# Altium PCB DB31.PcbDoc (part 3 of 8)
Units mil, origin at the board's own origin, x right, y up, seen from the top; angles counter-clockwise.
Board outline 3236.22 x 4456.69 mil, 8 copper layers (Top Layer, MidLayer1, MidLayer2, GND-Layer5, MidLayer3, VCC, MidLayer4, Bottom Layer), stack 61.8 mil thick; 226 components, 469 nets, 1815 pads, 1562 vias.
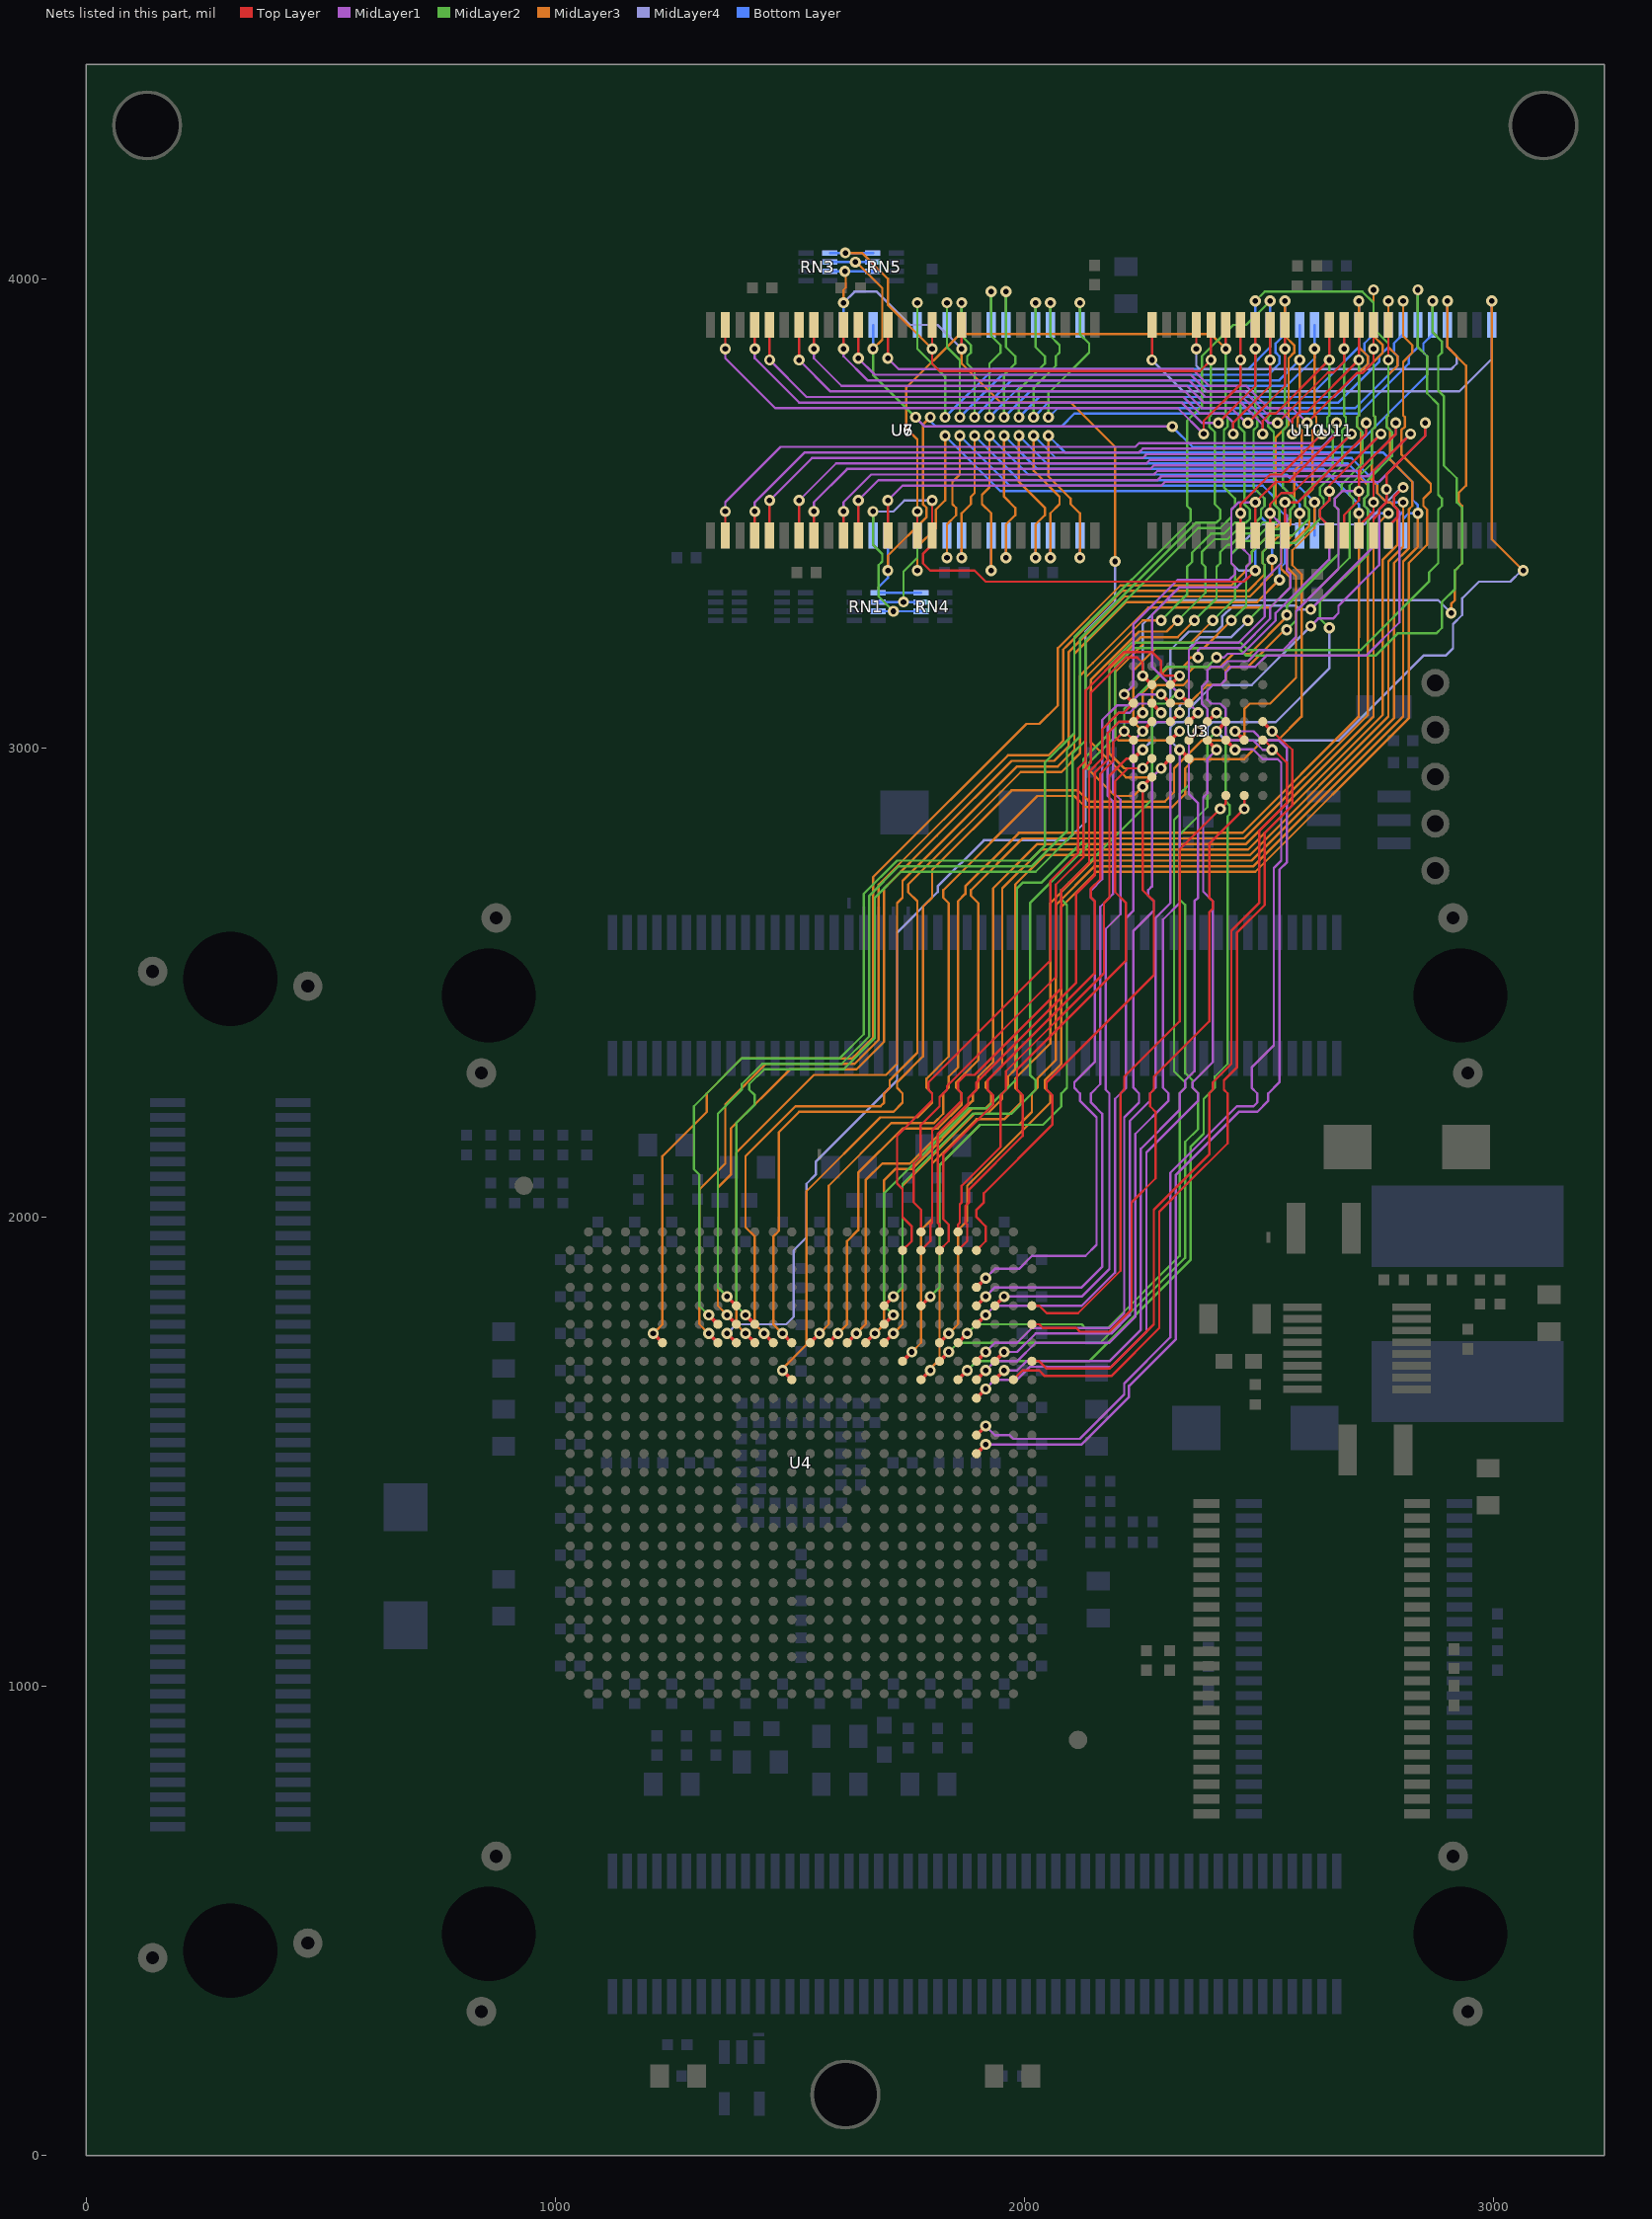
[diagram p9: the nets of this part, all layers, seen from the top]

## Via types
v1: diameter 23.62, hole 11.81, Top Layer to Bottom Layer, 947 vias
v2: diameter 23.62, hole 11.81, Top Layer to Bottom Layer, tented both sides, 476 vias
v3: diameter 27.56, hole 15.75, Top Layer to Bottom Layer, 138 vias
v4: diameter 23.62, hole 11.81, Top Layer to Bottom Layer, tented top, 1 vias

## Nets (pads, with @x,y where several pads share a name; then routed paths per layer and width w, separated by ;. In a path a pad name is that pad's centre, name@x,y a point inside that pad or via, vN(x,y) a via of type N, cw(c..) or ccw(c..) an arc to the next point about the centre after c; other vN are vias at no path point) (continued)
BUS_A19: U3.C4 U4.H21 U10.44 U11.44 | length 4321.2
  Top Layer w5: v2(2271.65,3826.77) U10.44@2271.65,3901.57
  Top Layer w7.87: U4.H21@1818.9,1692.91 v1(1838.59,1712.6) ; v1(2409.45,3035.43) U3.C4@2429.13,3056.1
  MidLayer2 w5: v1(1838.59,1712.6) 1858.27,1732.28 2078.74,1732.28 2090.55,1732.28 2161.42,1732.28 2342.52,1913.39 2342.52,2160.43 2370.08,2187.99 2370.08,2263.78 2358.27,2275.59 2358.27,2291.34 2342.52,2307.09 2342.52,2665.35 2330.71,2677.17 2330.71,2814.96 2389.76,2874.02 2389.76,3015.75 v1(2409.45,3035.43)
  MidLayer3 w5: v2(2996.06,3952.76) 2996.06,3633.86 2996.06,3444.88 v1(3062.99,3377.95)
  MidLayer4 w5: v2(2271.65,3826.77) 2338.58,3759.84 2926.67,3759.84 2996.06,3829.23 v2(2996.06,3952.76) ; v1(2409.45,3035.43) 2429.13,3015.75 2669.29,3015.75 2850.39,3196.85 2897.64,3196.85 2913.39,3212.6 2913.39,3263.78 2933.07,3283.46 2933.07,3318.9 2968.5,3354.33 3035.43,3354.33 3059.06,3377.95 v1(3062.99,3377.95)
  Bottom Layer w5: U11.44@2996.06,3901.57 v2(2996.06,3952.76)
BUS_A20: U3.D5 U4.K23 U10.28 U11.28 | length 3419.2
  Top Layer w5: v2(2775.59,3826.77) U10.28@2775.59,3901.57
  Top Layer w7.87: U4.K23@1897.64,1614.17 v1(1917.33,1633.86) ; U3.D5@2389.76,3016.73 v1(2409.45,2996.06)
  MidLayer1 w5: v1(1917.33,1633.86) 1937.01,1653.54 1984.25,1653.54 2011.81,1681.1 2078.74,1681.1 2090.55,1681.1 2185.04,1681.1 2259.84,1755.91 2259.84,2137.8 2370.08,2248.03 2370.08,2263.78 2358.27,2275.59 2358.27,2287.4 2401.57,2330.71 2401.57,2673.23 2380.91,2693.9 2380.91,2894.69 2389.76,2903.54 2389.76,2976.38 v1(2409.45,2996.06)
  MidLayer2 w5: v2(2492.13,3952.76) 2511.81,3972.44 2720.47,3972.44 2744.09,3948.82 2744.09,3893.7 2775.59,3862.21 v2(2775.59,3826.77) 2775.59,3708.66 2771.65,3704.72 2771.65,3685.04 2783.46,3673.23 2783.46,3622.05 2732.28,3570.87 2732.28,3539.37 2724.41,3531.5 2724.41,3515.75 2732.28,3507.87 2732.28,3413.39 2629.92,3311.02 2629.92,3275.59 v1(2649.61,3255.91)
  MidLayer4 w5: v1(2409.45,2996.06) 2389.76,3015.75 2389.76,3043.31 2401.57,3055.12 2535.43,3055.12 2649.61,3169.29 v1(2649.61,3255.91)
  Bottom Layer w5: U11.28@2492.13,3901.57 v2(2492.13,3952.76)
BUS_A21: U3.D4 U4.J22 | length 1840.2
  Top Layer w7.87: U4.J22@1858.27,1653.54 v1(1877.96,1673.23) ; U3.D4@2389.76,3056.1 v1(2409.45,3074.8)
  MidLayer2 w5: v1(1877.96,1673.23) 1897.64,1692.91 2078.74,1692.91 2090.55,1692.91 2137.8,1692.91 2354.33,1909.45 2354.33,2150.59 2381.89,2178.15 2381.89,2251.97 2405.51,2275.59 2405.51,2299.21 2433.07,2326.77 2433.07,2749.01 2433.07,2854.33 2437.01,2858.27 2437.01,2877.95 2429.13,2885.83 2429.13,2909.45 2429.13,3055.12 v1(2409.45,3074.8)
BUS_A22: U3.C5 U4.M23 | length 2028.4
  Top Layer w7.87: U4.M23@1897.64,1535.43 v1(1917.33,1555.12) ; U3.C5@2429.13,3016.73 v1@2448.82,2997.05
  MidLayer1 w5: v1(1917.33,1555.12) 1937.01,1535.43 1968.5,1535.43 1976.38,1527.56 2078.74,1527.56 2090.55,1527.56 2118.11,1527.56 2212.6,1622.05 2212.6,1645.67 2311.02,1744.09 2311.02,2094.49 2452.76,2236.22 2488.19,2236.22 2496.06,2244.09 2496.06,2263.78 2484.25,2275.59 2484.25,2318.9 2531.5,2366.14 2531.5,2744.09 2547.24,2759.84 2547.24,2968.5 2539.37,2976.38 2507.87,2976.38 2487.2,2997.05 v1@2448.82,2997.05
  Bottom Layer w5: v1@2447.83,2997.05 v1@2448.82,2997.05
  other v1: 2448.82,2996.06
BUS_A23: U3.B8 U4.F26 | length 1465
  Top Layer w5: U4.F26@2015.75,1771.65 2031.5,1771.65 2039.37,1763.78 2078.74,1763.78 2102.36,1763.78 2110.24,1763.78 2118.11,1755.91 2181.1,1755.91 2228.35,1803.15 2228.35,2031.5 2279.53,2082.68 2279.53,2224.41 2267.72,2236.22 2267.72,2263.78 2275.59,2271.65 2275.59,2299.21 2393.7,2417.32 2393.7,2649.61 2401.57,2657.48 2401.57,2673.23 2393.7,2681.1 2393.7,2731.56 ; 2393.7,2716.54 2393.7,2795.28 v1(2468.51,2870.08) U3.B8@2468.5,2898.62
BUS_A24: U3.C8 U4.E26 | length 1338.8
  Top Layer w5: U4.E26@2015.75,1811.02 2031.5,1811.02 2047.24,1795.28 2078.74,1795.28 2090.06,1795.28 2114.17,1795.28 2204.72,1885.83 2204.72,2263.78 2212.6,2271.65 2212.6,2299.21 2330.71,2417.32 2330.71,2783.46 v1(2417.32,2870.08) 2429.14,2881.89 U3.C8@2429.13,2898.62
BUS_D0: U3.E3 U4.E20 U6.2 U10.7 | length 3960.5
  Top Layer w5: U6.2@1362.21,3452.76 v2(1362.2,3503.93) ; U10.7@2460.63,3452.76 v1(2460.63,3500) 2460.63,3519.69 2523.62,3582.68 2547.24,3582.68 v2(2633.86,3669.29)
  Top Layer w7.87: U4.E20@1779.53,1811.02 v1(1799.21,1830.71) ; v1(2330.71,3114.17) U3.E3@2350.4,3095.48
  MidLayer1 w5: v2(1362.2,3503.93) 1362.2,3523.62 1480.31,3641.73 2236.22,3641.73 2244.09,3649.61 2614.17,3649.61 v2(2633.86,3669.29) ; v1(2330.71,3114.17) 2271.65,3173.23 2271.65,3283.46 2330.71,3342.52 2452.76,3342.52 2472.44,3362.2 2472.44,3385.83 2480.31,3393.7 2480.31,3409.45 2460.63,3429.13 v1(2460.63,3500)
  MidLayer2 w5: v1(1799.21,1830.71) 1818.9,1850.39 1818.9,2031.5 1818.9,2039.37 1818.9,2110.24 1905.51,2196.85 2039.37,2196.85 2078.74,2236.22 2078.74,2263.78 2090.55,2275.59 2090.55,2665.35 2078.74,2677.17 2078.74,2696.85 2094.49,2712.6 ; 2084.64,2702.76 2271.65,2889.77 2271.65,3086.61 2279.53,3094.49 2302.17,3094.49 2321.85,3114.17 v1(2330.71,3114.17)
BUS_D1: U3.H3 U4.B20 U6.4 U10.8 | length 3743.3
  Top Layer w5: U6.4@1425.2,3452.76 v2(1425.19,3503.93) ; U4.B20@1779.53,1929.13 1799.21,1948.82 1799.21,1984.25 1803.15,1988.19 1803.15,2031.5 1803.15,2039.37 1803.15,2185.04 1866.14,2248.03 1866.14,2263.78 1858.27,2271.65 1858.27,2287.4 1874.02,2303.15 1893.7,2303.15 2078.74,2488.19 2078.74,2696.85 2137.8,2755.91 2137.8,2949.54 2165.35,2977.1 2165.35,3039.37 2201.28,3075.3 2212.1,3075.3 U3.H3@2232.29,3095.48 ; U10.8@2492.13,3452.76 v1(2492.13,3523.62) 2535.43,3566.93 2562.99,3566.93 2665.35,3669.29 v2(2665.35,3692.91)
  Top Layer w7.87: v1(2212.6,3114.17) U3.H3@2232.29,3095.48
  MidLayer1 w5: v2(1425.19,3503.93) 1425.19,3523.62 1531.5,3629.92 2244.09,3629.92 2251.97,3637.8 2629.92,3637.8 2665.35,3673.23 v2(2665.35,3692.91) ; v1(2212.6,3114.17) 2232.28,3133.86 2232.28,3263.78 2326.77,3358.27 2437.01,3358.27 2448.82,3370.08 2448.82,3385.83 2440.94,3393.7 2440.94,3507.87 2456.69,3523.62 v1(2492.13,3523.62)
BUS_D2: U3.E4 U4.G22 U6.5 U10.9 | length 4029.6
  Top Layer w5: U6.5@1456.69,3452.76 v2(1456.69,3527.55) ; U10.9@2523.62,3452.76 v1(2523.62,3500) 2523.62,3519.69 2547.24,3543.31 2570.87,3543.31 v2(2696.85,3669.29)
  Top Layer w7.87: U4.G22@1858.27,1732.28 v1(1877.95,1751.97) ; U3.E4@2350.39,3056.1 v1(2370.08,3074.81)
  MidLayer1 w5: v2(1456.69,3527.55) 1547.24,3618.11 2251.97,3618.11 2259.84,3625.98 2653.54,3625.98 v2(2696.85,3669.29) ; v1(2370.08,3074.81) 2350.39,3094.5 2350.39,3208.66 2366.14,3224.41 2456.69,3224.41 2511.81,3279.53 2511.81,3358.27 2547.24,3393.7 2547.24,3476.38 v1(2523.62,3500)
  MidLayer2 w5: v1(1877.95,1751.97) 1897.64,1771.65 2082.68,1771.65 2090.55,1771.65 2122.05,1771.65 2129.92,1763.78 2177.17,1763.78 2330.71,1917.32 2330.71,2263.78 2342.52,2275.59 2342.52,2287.4 2318.9,2311.02 2318.9,2846.46 2330.71,2858.27 2330.71,2901.57 2350.39,2921.26 2350.39,3055.12 v1(2370.08,3074.81)
BUS_D3: U3.H4 U4.A21 U6.7 U10.10 | length 3663.5
  Top Layer w5: U6.7@1519.69,3452.76 v2(1519.68,3527.56) ; U4.A21@1818.9,1968.5 1818.9,1984.25 1814.96,1988.19 1814.96,2031.5 1814.96,2039.37 1814.96,2177.17 1879.92,2242.13 1879.92,2253.94 1897.64,2271.65 1897.64,2287.4 2110.24,2500 2110.24,2688.98 2149.61,2728.35 2149.61,2947.21 2177.17,2974.77 2177.17,3031.5 2201.78,3056.11 U3.H4@2232.28,3056.1 ; U10.10@2555.12,3452.76 v1(2555.12,3523.62) 2582.68,3523.62 2640.75,3581.69 2728.35,3669.29 v2(2728.35,3692.91)
  Top Layer w7.87: U3.H4@2232.28,3056.1 v1@2251.47,3075.3
  MidLayer1 w5: v2(1519.68,3527.56) 1598.43,3606.3 2259.84,3606.3 2267.72,3614.17 2673.23,3614.17 2728.35,3669.29 v2(2728.35,3692.91) ; v1(2370.08,3192.91) 2370.08,3208.66 2374.02,3212.6 2460.63,3212.6 2523.62,3275.59 2523.62,3299.21 2566.93,3342.52 2566.93,3370.08 2559.06,3377.95 2559.06,3496.06 2555.12,3500 v1(2555.12,3523.62)
  MidLayer3 w5: v1(2251.97,3074.8) 2251.97,3118.11 2255.91,3122.05 2307.09,3173.23 2338.58,3173.23 2350.39,3185.04 2350.39,3188.98 2354.33,3192.91 v1(2370.08,3192.91)
BUS_D4: U3.H5 U4.B21 U6.8 U10.13 | length 3728.5
  Top Layer w5: U6.8@1551.18,3452.76 v2(1551.18,3503.94) ; U4.B21@1818.9,1929.13 1838.58,1948.82 1838.58,1984.25 1826.77,1996.06 1826.77,2031.5 1826.77,2039.37 1826.77,2133.86 1933.07,2240.16 1933.07,2259.84 1921.26,2271.65 1921.26,2291.34 2149.61,2519.69 2149.61,2673.23 2141.73,2681.1 2141.73,2700.79 2161.42,2720.47 2161.42,2944.88 2188.98,2972.44 2188.98,3011.81 v1(2212.6,3035.43) U3.H5@2232.28,3016.73 ; U10.13@2649.61,3452.76 2649.61,3472.44 2629.92,3492.13 2629.92,3507.87 2649.61,3527.56 v1(2649.61,3547.24) 2649.61,3559.06 v2(2759.84,3669.29)
  MidLayer1 w5: v2(1551.18,3503.94) 1551.18,3523.62 1622.05,3594.49 2267.72,3594.49 2275.59,3602.36 2692.91,3602.36 v2(2759.84,3669.29) ; v1(2409.45,3192.91) 2425.2,3192.91 2433.07,3200.79 2464.57,3200.79 2535.43,3271.65 2535.43,3287.4 2649.61,3401.57 2649.61,3472.44 2629.92,3492.13 2629.92,3507.87 2649.61,3527.56 v1(2649.61,3547.24)
  MidLayer2 w5: v1(2212.6,3035.43) 2212.6,3082.68 2303.15,3173.23 2389.76,3173.23 v1(2409.45,3192.91)
BUS_D5: U3.E5 U4.J24 U6.10 U10.14 | length 4118.2
  Top Layer w5: U6.10@1614.17,3452.76 v2(1614.17,3503.93) ; U10.14@2681.1,3452.76 2681.1,3496.06 2712.6,3527.56 v1(2712.6,3547.24) 2712.6,3590.55 2791.34,3669.29 v2(2791.34,3692.91)
  Top Layer w7.87: U4.J24@1937.01,1653.54 v1(1956.7,1673.23) ; U3.E5@2350.39,3016.73 v1(2370.08,3035.43)
  MidLayer1 w5: v2(1614.17,3503.93) 1614.17,3523.62 1673.23,3582.68 2275.59,3582.68 2283.46,3590.55 2712.6,3590.55 2791.34,3669.29 v2(2791.34,3692.91) ; v1(1956.7,1673.23) 1984.25,1673.23 2003.94,1692.91 2078.74,1692.91 2090.55,1692.91 2181.1,1692.91 2248.03,1759.84 2248.03,2145.67 2330.71,2228.35 2330.71,2263.78 2342.52,2275.59 2342.52,2291.34 2362.2,2311.02 2362.2,2673.23 2370.08,2681.1 2370.08,2720.47 ; 2370.08,2704.72 2370.08,2720.47 ; v1(2712.6,3547.24) 2677.17,3547.24 2661.42,3531.5 2661.42,3515.75 2669.29,3507.87 2669.29,3381.89 2578.74,3291.34 2578.74,3236.22 2551.18,3208.66 2500,3208.66 2476.38,3185.04 2433.07,3185.04 2421.26,3173.23 2397.64,3173.23 2389.76,3165.35 2389.76,3141.73 2377.95,3129.92 2377.95,3094.49 2389.76,3082.68 2389.76,3055.12 v1(2370.08,3035.43) 2350.39,3015.75 2350.39,2901.57 2370.08,2881.89 2370.08,2720.47
BUS_D6: U3.H6 U4.A22 U6.11 U10.15 | length 3658.7
  Top Layer w5: U6.11@1645.67,3452.76 v2(1645.66,3527.55) ; U4.A22@1858.27,1968.5 1858.27,1984.25 1862.2,1988.19 1862.2,2027.56 1866.14,2031.5 1866.14,2039.37 1866.14,2066.93 1948.82,2149.6 1948.82,2259.84 1960.63,2271.65 1960.63,2311.02 2169.29,2519.69 2169.29,2669.29 2181.1,2681.1 2181.1,2940.94 2217.52,2977.37 U3.H6@2232.28,2977.36 ; U10.15@2712.6,3452.76 2712.6,3472.44 2744.09,3503.94 v1(2744.09,3523.62) 2744.09,3590.55 v2(2822.83,3669.29)
  Top Layer w7.87: U3.H6@2232.28,2977.36 2251.47,2996.56 v1@2251.97,2997.05
  MidLayer1 w5: v2(1645.66,3527.55) 1688.98,3570.87 2283.46,3570.87 2291.34,3578.74 2732.28,3578.74 v2(2822.83,3669.29) ; v1(2610.24,3295.28) 2744.09,3429.13 v1(2744.09,3523.62)
  MidLayer4 w5: v1(2251.97,2996.06) 2271.65,3015.75 2271.65,3043.31 2283.46,3055.12 2303.15,3055.12 2311.02,3062.99 2311.02,3208.66 2350.39,3248.03 2409.45,3248.03 2421.26,3259.84 2421.26,3279.53 2444.88,3303.15 2578.74,3303.15 2586.61,3295.28 v1(2610.24,3295.28)
BUS_D7: U3.E6 U4.J23 U6.13 U10.16 | length 4121.2
  Top Layer w5: U6.13@1708.66,3452.76 v2(1708.66,3527.55) ; U10.16@2744.09,3452.76 2744.09,3488.19 2755.91,3500 2755.91,3507.87 2771.65,3523.62 v1(2771.65,3551.18) 2771.65,3582.68 2854.33,3665.35 v2(2854.33,3692.91)
  Top Layer w7.87: U4.J23@1897.64,1653.54 v1(1917.33,1673.23) ; v1@2330.71,2997.05 2331.2,2996.56 U3.E6@2350.39,2977.36
  MidLayer1 w5: v2(1708.66,3527.55) 1740.16,3559.06 2291.34,3559.06 2299.21,3566.93 2755.91,3566.93 2854.33,3665.35 v2(2854.33,3692.91) ; v1(1917.33,1673.23) 1937.01,1692.91 1984.25,1692.91 2023.62,1732.28 2078.74,1732.28 2090.55,1732.28 2181.1,1732.28 2236.22,1787.4 2236.22,2177.17 2307.09,2248.03 2307.09,2263.78 2295.28,2275.59 2295.27,2633.86 2330.71,2669.29 2330.71,2700.79 ; 2330.71,2681.1 v1(2330.71,2996.06) v1@2330.71,2997.05 ; v1(2610.24,3259.84) 2625.98,3275.59 2657.48,3275.59 2669.29,3287.4 2669.29,3303.15 2755.91,3389.76 2755.91,3507.87 2771.65,3523.62 v1(2771.65,3551.18)
  MidLayer4 w5: v1(2330.71,2996.06) 2311.02,3015.75 2311.02,3043.31 2322.83,3055.12 2338.58,3055.12 2350.39,3066.93 2350.39,3082.68 2401.57,3133.86 2484.25,3133.86 v1(2610.24,3259.84)
BUS_D8: U3.F3 U4.D23 U6.42 U10.29 | length 3972.1
  Top Layer w5: v2(1708.66,3830.71) U6.42@1708.66,3901.57 ; v2(2602.36,3692.91) 2708.17,3798.72 2719.98,3798.72 2744.09,3822.83 v2(2744.09,3850.39) U10.29@2744.09,3901.57
  Top Layer w7.87: U4.D23@1897.64,1850.39 v1(1917.33,1870.08) ; v1@2291.34,3115.16 2291.83,3114.67 U3.F3@2311.03,3095.48
  MidLayer1 w5: v2(1708.66,3830.71) 1732.28,3807.09 2358.27,3807.09 2393.7,3771.65 2472.44,3771.65 2519.69,3724.41 2570.87,3724.41 v2(2602.36,3692.91) ; v1(1917.33,1870.08) 1937.01,1889.76 1988.19,1889.76 2015.75,1917.32 2078.74,1917.32 2090.55,1917.32 2129.92,1917.32 2153.54,1940.94 2153.54,2212.6 2118.11,2248.03 2118.11,2263.78 2106.3,2275.59 2106.3,2287.4 2149.61,2330.71 2149.61,2645.67 2149.61,2673.23 2141.73,2681.1 2141.73,2696.85 2165.35,2720.47 2165.35,3059.06 2196.85,3090.55 2220.47,3090.55 2244.09,3114.17 v1(2291.34,3114.17)
  MidLayer2 w5: v1(2559.06,3251.97) 2578.74,3271.65 2578.74,3291.34 2692.91,3405.51 2692.91,3507.87 2700.79,3515.75 2700.79,3531.5 2692.91,3539.37 2692.91,3559.06 2740.16,3606.3 2740.16,3677.17 2748.03,3685.04 2748.03,3704.72 2744.09,3708.66 v2(2744.09,3850.39)
  MidLayer3 w5: v1(2291.34,3114.17) 2311.02,3094.49 2350.39,3094.49 2389.76,3133.86 2417.32,3133.86 2429.13,3145.67 2429.13,3165.35 2437.01,3173.23 2476.38,3173.23 2555.12,3251.97 v1(2559.06,3251.97)
BUS_D9: U3.G3 U4.E23 U6.44 U10.30 | length 4107.5
  Top Layer w5: v2(1645.67,3830.71) U6.44@1645.67,3901.57 ; v2(2570.87,3669.29) 2570.87,3700.79 2586.61,3716.54 2602.36,3716.54 v2(2712.6,3826.77) U10.30@2712.6,3901.57
  Top Layer w7.87: U4.E23@1897.64,1811.02 v1(1917.33,1830.71) ; U3.G3@2271.65,3095.48 v1(2291.34,3074.8)
  MidLayer1 w5: v2(1645.67,3830.71) 1681.1,3795.28 2354.33,3795.28 2389.76,3759.84 2469,3759.84 2516.24,3712.6 2551.18,3712.6 2570.87,3692.91 v2(2570.87,3669.29) ; v1(1917.33,1830.71) 1937.01,1850.39 2078.74,1850.39 2090.55,1850.39 2122.05,1850.39 2165.35,1893.7 2165.35,2220.47 2141.73,2244.09 2141.73,2263.78 2161.42,2283.46 2161.42,2661.42 2188.98,2688.98 2188.98,2724.41 ; 2188.98,2700.79 2188.98,2885.83 2177.17,2897.64 2177.17,3051.18 2200.79,3074.8 2224.41,3074.8 2244.09,3094.49 2271.65,3094.49 v1(2291.34,3074.8)
  MidLayer2 w5: v1(2559.06,3283.46) 2559.06,3303.15 2669.29,3413.39 2669.29,3507.87 2661.42,3515.75 2661.42,3531.5 2676.18,3546.26 2676.18,3562.01 2720.47,3606.3 2720.47,3673.23 2708.66,3685.04 2708.66,3704.72 2712.6,3708.66 v2(2712.6,3826.77)
  MidLayer3 w5: v1(2291.34,3074.8) 2271.65,3094.49 2271.65,3122.05 2283.46,3133.86 2338.58,3133.86 2350.39,3145.67 2350.39,3161.42 2362.2,3173.23 2417.32,3173.23 2444.88,3200.79 2480.31,3200.79 2559.06,3279.53 v1(2559.06,3283.46)
BUS_D10: U3.F4 U4.E24 U6.45 U10.31 | length 3968.9
  Top Layer w5: v2(1614.17,3850.39) U6.45@1614.17,3901.57 ; v2@2537.4,3694.88 2539.37,3694.88 2541.34,3694.88 2646.65,3800.2 2658.46,3800.2 2681.1,3822.83 v2(2681.1,3850.39) U10.31@2681.1,3901.57
  Top Layer w7.87: U4.E24@1937.01,1811.02 v1(1956.7,1830.71) ; U3.F4@2311.02,3056.1 v1(2330.71,3074.8)
  MidLayer1 w5: v2(1614.17,3850.39) 1614.17,3834.65 1665.35,3783.46 2350.39,3783.46 2385.83,3748.03 2464.57,3748.03 2519.69,3692.91 v2(2539.37,3692.91) ; v1(1956.7,1830.71) 2078.74,1830.71 2090.55,1830.71 2122.05,1830.71 2181.1,1889.76 2181.1,2263.78 2173.23,2271.66 2173.23,2614.17 2204.72,2645.67 2204.72,2889.76 2188.98,2905.51 2188.98,3043.31 2200.79,3055.12 2311.02,3055.12 v1(2330.71,3074.8)
  MidLayer2 w5: v1(2476.38,3271.65) 2511.81,3307.09 2511.81,3389.76 2507.87,3393.7 2507.87,3417.32 2527.56,3437.01 2578.74,3437.01 2629.92,3488.19 2629.92,3507.87 2637.8,3515.75 2637.8,3531.5 2629.92,3539.37 2629.92,3555.12 2677.16,3602.36 2677.16,3677.17 2685.04,3685.04 2685.04,3704.72 2681.1,3708.66 v2(2681.1,3850.39)
  MidLayer4 w5: v1(2330.71,3074.8) 2330.71,3090.55 2334.65,3094.49 2342.52,3094.49 2350.39,3102.36 2350.39,3212.6 2374.02,3236.22 2440.94,3236.22 v1(2476.38,3271.65)
BUS_D11: U3.G4 U4.F23 U6.47 U10.32 | length 4029.9
  Top Layer w5: v2(1551.18,3850.39) U6.47@1551.18,3901.57 ; v2(2507.87,3669.29) 2507.87,3696.85 2523.62,3712.6 2535.43,3712.6 v2(2649.61,3826.77) U10.32@2649.61,3901.57
  Top Layer w7.87: U4.F23@1897.64,1771.65 v1(1917.33,1791.34) ; v1(2251.97,3035.43) U3.G4@2271.65,3056.1
  MidLayer1 w5: v2(1551.18,3850.39) 1551.18,3830.71 1610.24,3771.65 2346.46,3771.65 2381.89,3736.22 2460.63,3736.22 2507.87,3688.98 v2(2507.87,3669.29) ; v1(1917.33,1791.34) 1937.01,1811.02 1976.38,1811.02 2078.74,1811.02 2090.55,1811.02 2122.05,1811.02 2192.91,1881.89 2192.91,2251.97 2216.53,2275.59 2216.54,2637.8 2232.28,2653.54 2232.28,2669.29 2232.28,3015.75 v1(2251.97,3035.43)
  MidLayer2 w5: v1(2440.94,3271.65) 2472.44,3303.15 2472.44,3385.83 2484.25,3397.64 2484.25,3417.32 2519.69,3452.76 2570.87,3452.76 2606.3,3488.19 2606.3,3507.87 2598.43,3515.75 2598.43,3543.31 2657.48,3602.36 2657.48,3673.23 2645.67,3685.04 2645.67,3704.72 2649.61,3708.66 v2(2649.61,3826.77)
  MidLayer3 w5: v1(2251.97,3035.43) 2232.28,3055.12 2232.28,3165.35 2279.53,3212.6 2381.89,3212.6 v1(2440.94,3271.65)
BUS_D12: U3.F5 U4.H24 U6.48 U10.35 | length 4217.9
  Top Layer w5: v2(1519.68,3826.77) U6.48@1519.69,3901.57 ; v2(2476.38,3692.91) 2555.12,3771.65 v2(2555.12,3850.39) U10.35@2555.12,3901.57
  Top Layer w7.87: U4.H24@1937.01,1692.91 v1(1956.7,1712.6) ; U3.F5@2311.02,3016.73 v1(2330.71,3035.43)
  MidLayer1 w5: v2(1519.68,3826.77) 1586.6,3759.84 2342.52,3759.84 2377.95,3724.41 2440.94,3724.41 2472.44,3692.91 v2(2476.38,3692.91) ; v1(1956.7,1712.6) 1984.25,1712.6 2023.62,1751.97 2078.74,1751.97 2090.55,1751.97 2185.04,1751.97 2224.41,1791.34 2224.41,2204.72 2267.72,2248.03 2267.72,2263.78 2279.53,2275.59 2279.53,2637.79 2311.02,2669.29 2311.02,3015.75 v1(2330.71,3035.43) 2330.22,3035.93 v1@2326.78,3039.37
  MidLayer2 w5: v1(2401.57,3271.65) 2448.82,3318.9 2448.82,3385.83 2440.94,3393.7 2440.94,3413.39 2468.5,3440.94 2488.19,3440.94 2513.78,3466.54 2541.34,3466.54 2547.24,3472.44 2566.93,3492.13 2566.93,3507.87 2574.8,3515.75 2574.8,3531.5 2555.12,3551.18 2551.18,3555.12 2551.18,3677.17 2559.05,3685.04 2559.05,3704.72 2555.12,3708.66 v2(2555.12,3850.39)
  MidLayer3 w5: v1(2330.71,3035.43) 2311.02,3015.75 2200.79,3015.75 2192.91,3023.62 2192.91,3161.42 2255.91,3224.41 2354.33,3224.41 v1(2401.57,3271.65)
BUS_D13: U3.G6 U4.B22 U6.50 U10.36 | length 3854.6
  Top Layer w5: v2(1456.69,3826.77) U6.50@1456.69,3901.57 ; U4.B22@1858.27,1929.13 1877.95,1948.82 1877.95,1984.25 1874.02,1988.19 1874.02,2023.62 1881.89,2031.5 1881.89,2039.37 1881.89,2059.05 1996.06,2173.23 1996.06,2259.84 1984.25,2271.65 1984.25,2314.96 2216.54,2547.24 2216.54,2669.29 2192.91,2692.91 2192.91,2838.58 ; 2192.91,2822.83 2192.91,2929.14 2220.47,2956.69 v1(2251.97,2956.69) ; v1@2251.97,2957.68 U3.G6@2271.65,2977.36 ; v2(2444.88,3669.29) 2444.88,3692.91 2523.62,3771.65 v2(2523.62,3826.77) U10.36@2523.62,3901.57
  MidLayer1 w5: v2(1456.69,3826.77) 1535.43,3748.03 2338.58,3748.03 2374.02,3712.6 2425.2,3712.6 2444.88,3692.91 v2(2444.88,3669.29)
  MidLayer2 w5: v1(2362.2,3271.65) 2409.45,3318.9 2409.45,3385.83 2417.32,3393.7 2417.32,3417.32 2433.07,3433.07 2440.94,3433.07 2464.57,3456.69 2484.25,3456.69 2507.87,3480.32 2523.62,3480.32 2535.43,3480.31 2543.31,3488.19 2543.31,3507.87 2531.5,3519.69 2531.5,3673.23 2519.68,3685.04 2519.68,3704.72 2523.62,3708.66 v2(2523.62,3826.77)
  MidLayer3 w5: v1(2251.97,2956.69) 2212.6,2956.69 2181.1,2988.19 2181.1,3169.29 2248.03,3236.22 2326.77,3236.22 v1(2362.2,3271.65)
BUS_D14: U3.F6 U4.H23 U6.51 U10.37 | length 4224.3
  Top Layer w5: v2(1425.2,3850.39) U6.51@1425.2,3901.57 ; v2(2413.38,3692.91) 2492.13,3771.65 v2(2492.13,3850.39) U10.37@2492.13,3901.57
  Top Layer w7.87: U4.H23@1897.64,1692.91 v1(1917.33,1712.6) ; v1@2290.85,2957.19 U3.F6@2311.02,2977.36
  MidLayer1 w5: v2(1425.2,3850.39) 1425.2,3830.71 1519.69,3736.22 2334.65,3736.22 2377.95,3692.91 v2(2413.38,3692.91) ; v1(1917.33,1712.6) 1937.01,1732.28 1984.25,1732.28 2015.75,1763.78 2078.74,1763.78 2090.55,1763.78 2181.1,1763.78 2212.6,1795.28 2212.6,2212.6 2244.09,2244.09 2244.09,2263.78 2232.28,2275.59 2232.28,2610.24 2275.59,2653.54 2275.59,2673.23 2263.78,2685.04 2263.78,2696.85 2271.65,2704.72 2271.65,2937.01 v1(2291.34,2956.69) v1@2291.34,2957.68
  MidLayer2 w5: v1(2326.77,3271.65) 2385.83,3330.71 2385.83,3385.83 2377.95,3393.7 2377.95,3417.32 2405.51,3444.88 2433.07,3444.88 2456.69,3468.5 2480.31,3468.5 2503.94,3492.13 2503.94,3507.87 2511.81,3515.75 2511.81,3531.5 2492.13,3551.18 2488.19,3555.12 2488.19,3677.17 2496.06,3685.04 2496.06,3704.72 2492.13,3708.66 v2(2492.13,3850.39)
  MidLayer3 w5: v1(2291.34,2956.69) 2271.66,2937.01 2216.54,2937.01 2141.73,3011.81 2141.73,3145.67 2244.09,3248.03 2303.15,3248.03 v1(2326.77,3271.65)
BUS_D15: U3.G7 U4.B23 U6.53 U10.38 | length 3868
  Top Layer w5: v2(1362.2,3850.39) U6.53@1362.21,3901.57 ; U4.B23@1897.64,1929.13 1917.32,1948.82 1917.32,1980.32 1897.64,2000 1897.64,2015.75 1913.39,2031.5 1913.39,2039.37 1913.39,2051.18 2059.05,2196.85 2059.05,2259.84 2047.24,2271.65 2047.24,2287.4 2275.59,2515.75 2275.59,2673.23 2251.97,2696.85 2251.97,2819.14 ; 2251.97,2814.96 v1(2251.97,2917.32) v1@2251.97,2918.31 ; v2(2381.89,3669.29) 2381.89,3696.85 2460.63,3775.59 v2(2460.63,3826.77) U10.38@2460.63,3901.57
  Top Layer w7.87: v1@2251.97,2918.31 U3.G7@2271.65,2937.99
  MidLayer1 w5: v2(1362.2,3850.39) 1362.2,3830.71 1468.5,3724.41 2326.77,3724.41 v2(2381.89,3669.29)
  MidLayer2 w5: v1(2291.34,3271.65) 2346.46,3326.77 2346.46,3385.83 2357.28,3396.65 2357.28,3416.34 2397.64,3456.69 2425.2,3456.69 2448.82,3480.32 2472.44,3480.32 2480.31,3488.19 2480.31,3507.87 2468.5,3519.69 2468.5,3673.23 2456.69,3685.04 2456.69,3704.72 2460.63,3708.66 v2(2460.63,3826.77)
  MidLayer3 w5: v1(2251.97,2917.32) 2232.28,2897.64 2192.91,2897.64 2129.92,2960.63 2129.92,3149.61 2251.97,3271.65 v1(2291.34,3271.65)
BUS_D16: U4.J20 U7.2 U11.7 | length 3826.7
  Top Layer w7.87: U4.J20@1779.53,1653.54 v1(1799.22,1673.23)
  MidLayer3 w5: v1(1799.22,1673.23) 1799.22,1677.17 1818.9,1696.85 1818.9,2031.5 1818.9,2039.37 1818.9,2110.24 1905.51,2196.85 1988.19,2196.85 2015.75,2224.41 2015.75,2263.78 2027.56,2275.59 2027.56,2295.27 2066.93,2334.64 2066.93,2665.35 2149.61,2748.03 2488.19,2748.03 2807.09,3066.93 2807.09,3141.73 2807.09,3229.33 2807.09,3377.95 2807.09,3397.64 2838.58,3429.13 v2(2838.58,3500) ; v2(2051.18,3665.35) 2051.18,3578.74 2098.43,3531.5 2098.43,3519.68 2118.11,3500 v2(2118.11,3405.51)
  Bottom Layer w5: v2(2051.18,3665.35) 2086.61,3629.92 2763.78,3629.92 2826.77,3566.93 2826.77,3529.53 2838.58,3517.72 v2(2838.58,3500) 2818.9,3500 2807.09,3488.19 U11.7@2807.09,3452.76 ; v2(2118.11,3405.51) U7.2@2118.11,3452.76
BUS_D17: U4.G18 U7.4 U11.8 | length 3801.3
  Top Layer w7.87: U4.G18@1700.79,1732.28 v1(1720.47,1751.97)
  MidLayer3 w5: v1(1720.47,1751.97) 1740.16,1771.65 1740.16,2031.49 1740.16,2039.37 1740.16,2066.93 1893.7,2220.47 1921.26,2220.47 1952.76,2251.97 1952.76,2263.78 1964.57,2275.59 1964.57,2299.21 1980.31,2314.96 1980.31,2708.66 2043.31,2771.65 2480.31,2771.65 2775.59,3066.93 2775.59,3397.64 2807.09,3429.13 v2(2807.09,3523.62) ; v2(2019.68,3665.35) 2019.68,3590.55 2074.8,3535.43 2074.8,3519.68 2055.12,3500 v2(2055.12,3405.51)
  Bottom Layer w5: v2(2019.68,3665.35) 2066.93,3618.11 2696.85,3618.11 2751.97,3562.99 2751.97,3543.31 2771.65,3523.62 v2(2807.09,3523.62) 2807.09,3503.94 2775.59,3472.44 U11.8@2775.59,3452.76 ; v2(2055.12,3405.51) U7.4@2055.12,3452.76
BUS_D18: U4.G16 U7.5 U11.9 | length 3821
  Top Layer w7.87: U4.G16@1622.05,1732.28 v1(1641.73,1751.97)
  MidLayer3 w5: v1(1641.73,1751.97) 1661.42,1771.65 1661.42,2031.49 1661.42,2039.37 1661.42,2078.74 1696.85,2114.17 1755.91,2114.17 1889.76,2248.03 1889.76,2263.78 1901.57,2275.59 1901.57,2299.21 1933.07,2330.71 1933.07,2700.79 2027.56,2795.28 2472.44,2795.28 2744.09,3066.93 2744.09,3468.5 v2(2775.59,3500) ; v2(1988.19,3665.35) 1988.19,3566.93 2042.85,3512.27 2043.31,3512.27 2043.31,3496.06 2023.62,3476.38 v2(2023.62,3405.51)
  Bottom Layer w5: v2(1988.19,3665.35) 2047.24,3606.3 2688.98,3606.3 2732.28,3562.99 2732.28,3539.37 2724.41,3531.5 2724.41,3515.75 2740.16,3500 2744.09,3500 ; v2(2023.62,3405.51) U7.5@2023.62,3452.76 ; U11.9@2744.09,3452.76 2744.09,3500 ; v2(2775.59,3500) 2744.09,3500
BUS_D19: U4.G14 U7.7 U11.10 | length 3792.4
  Top Layer w7.87: U4.G14@1543.31,1732.28 v1(1562.99,1751.97)
  MidLayer3 w5: v1(1562.99,1751.97) 1582.68,1771.65 1582.68,2031.49 1582.68,2039.37 1582.68,2066.93 1716.54,2200.79 1807.09,2200.79 1826.77,2220.47 1826.77,2263.78 1838.58,2275.59 1838.58,2299.21 1858.27,2318.9 1858.27,2673.23 1874.02,2688.98 1874.02,2704.72 1988.19,2818.9 2464.57,2818.9 2712.6,3066.93 ; v2(1956.69,3665.35) 1956.69,3535.43 1980.31,3511.81 1980.31,3496.06 1960.63,3476.38 v2(1960.63,3405.51) ; 2712.46,3066.93 2712.57,3401.57 v2(2712.6,3500)
  Bottom Layer w5: v2(1956.69,3665.35) 2027.56,3594.49 2637.8,3594.49 2712.6,3519.69 v2(2712.6,3500) U11.10@2712.6,3452.76 ; v2(1960.63,3405.51) U7.7@1960.63,3452.76
BUS_D20: U4.J13 U7.8 U11.13 | length 3907.8
  Top Layer w7.87: v1(1484.25,1673.23) U4.J13@1503.94,1653.54
  MidLayer3 w5: v1@1484.25,1677.16 1535.43,1728.34 1535.43,2031.49 1535.43,2039.37 1535.43,2055.12 1692.91,2212.6 1771.65,2212.6 1803.15,2244.09 1803.15,2263.78 1791.34,2275.59 1791.34,2295.27 1838.58,2342.52 1838.58,2669.29 1826.77,2681.1 1826.77,2696.85 2027.56,2897.64 2106.3,2897.64 2129.92,2874.02 2314.96,2874.02 2342.52,2901.57 2342.52,2956.69 2362.2,2976.38 2468.5,2976.38 2507.87,3015.75 2539.37,3015.75 2590.55,3066.93 2590.55,3370.08 2570.87,3389.76 2570.87,3421.26 2618.11,3468.5 v2(2618.11,3523.62) ; v2(1925.2,3665.35) 1925.2,3555.12 1909.45,3539.37 1909.45,3519.68 1929.13,3500 v2(1929.13,3377.95)
  Bottom Layer w5: v2(1925.2,3665.35) 2007.87,3582.68 2559.06,3582.68 v2(2618.11,3523.62) 2618.11,3500 U11.13@2618.11,3452.76 ; v2(1929.13,3377.95) U7.8@1929.13,3452.76
BUS_D21: U4.G12 U7.10 U11.14 | length 3761.7
  Top Layer w7.87: v1(1444.88,1751.97) U4.G12@1464.57,1732.28
  MidLayer3 w5: v1(1444.88,1751.97) 1425.2,1771.66 1425.2,1836.62 1425.2,1958.66 1405.51,1978.35 1405.51,2031.5 1405.51,2039.37 1405.51,2129.92 1511.81,2236.22 1692.91,2236.22 1700.79,2244.09 1700.79,2263.78 1712.6,2275.59 1712.6,2291.34 1771.65,2350.39 1771.65,2673.23 1751.97,2692.91 1751.97,2708.66 1992.13,2948.82 2078.74,2948.82 2118.11,2988.19 2118.11,3153.54 2145.67,3181.1 2263.78,3299.21 2523.62,3299.21 2566.93,3342.52 2566.93,3362.2 2547.24,3381.89 2547.24,3429.13 2586.61,3468.5 v2(2586.61,3500) ; v2(1866.14,3405.51) 1866.14,3500 1885.83,3519.68 1885.83,3535.43 1893.7,3543.31 v2(1893.7,3665.35)
  Bottom Layer w5: v2(1866.14,3405.51) U7.10@1866.14,3452.76 ; v2(1893.7,3665.35) 1988.19,3570.87 2535.43,3570.87 2586.61,3519.69 v2(2586.61,3500) U11.14@2586.61,3452.76
BUS_D22: U4.G11 U7.11 U11.15 | length 3666.1
  Top Layer w7.87: v1(1405.51,1751.97) U4.G11@1425.2,1732.28
  MidLayer3 w5: v1(1405.51,1751.97) 1385.83,1771.66 1385.83,2031.5 1385.83,2039.37 1385.83,2137.8 1551.18,2303.15 1704.72,2303.15 1728.35,2326.77 1728.35,2669.29 1740.16,2681.1 1740.16,2716.54 1984.25,2960.63 2070.87,2960.63 2106.3,2996.06 2106.3,3200.79 2216.54,3311.02 2496.06,3311.02 v1(2543.31,3358.27) ; v2(1834.65,3405.51) 1834.65,3476.38 1854.33,3496.06 1854.33,3511.81 1846.46,3519.69 1846.46,3566.93 1862.2,3582.68 v2(1862.2,3665.35)
  Bottom Layer w5: v2(1834.65,3405.51) U7.11@1834.65,3452.76 ; v2(1862.2,3665.35) 1968.5,3559.06 2507.87,3559.06 2535.43,3531.5 2535.43,3515.75 2555.12,3496.06 U11.15@2555.12,3452.76 2555.12,3417.32 2555.12,3393.7 2543.31,3381.89 v1(2543.31,3358.27)
BUS_D23: U4.F10 U7.13 U11.16 | length 3706.6
  Top Layer w7.87: v1(1366.14,1791.34) U4.F10@1385.83,1771.65
  MidLayer3 w5: v1(1366.14,1791.34) 1346.46,1811.02 1346.46,2031.49 1346.46,2039.37 1346.46,2062.99 1374.02,2090.55 1374.02,2188.98 1500,2314.96 1641.73,2314.96 1700.79,2374.02 1700.79,2700.79 1812.99,2812.99 1972.44,2972.44 2062.99,2972.44 2094.49,3003.94 2094.49,3204.72 2212.6,3322.83 2480.31,3322.83 2527.56,3370.08 2527.56,3381.89 ; v2(1771.65,3377.95) 1771.65,3429.13 1811.02,3468.5 1811.02,3507.87 1830.71,3527.56 v2(1830.71,3665.35) ; 2527.56,3369.83 v2(2527.56,3401.57)
  Bottom Layer w5: v2(1771.65,3377.95) U7.13@1771.65,3452.76 ; v2(1830.71,3665.35) 1948.82,3547.24 2496.06,3547.24 2511.81,3531.5 2511.81,3515.75 2503.94,3507.87 2503.94,3492.13 2523.62,3472.44 U11.16@2523.62,3452.76 2527.56,3448.82 v2(2527.56,3401.57)
BUS_D24: U4.F9 U7.42 U11.29 | length 4190.7
  Top Layer w7.87: v1(1326.77,1791.34) U4.F9@1346.46,1771.65
  MidLayer2 w5: v1(1326.77,1791.34) 1307.09,1811.03 1307.09,2031.5 1307.09,2039.37 1307.09,2090.55 1295.28,2102.36 1295.28,2236.22 1397.64,2338.58 1606.3,2338.58 1657.48,2389.76 1657.48,2688.98 1728.35,2759.84 2011.81,2759.84 2043.31,2791.34 2043.31,2968.5 2106.3,3031.5 2106.3,3236.22 2354.33,3484.25 2354.33,3507.87 2346.46,3515.75 2346.46,3696.85 2377.95,3728.35 2377.95,3834.65 2444.88,3901.57 2472.77,3901.57 v2(2523.62,3952.42) ; v2(1771.65,3948.82) 1771.65,3850.39 1830.71,3791.34 v2(1830.71,3704.72)
  Bottom Layer w5: U7.42@1771.65,3901.57 v2(1771.65,3948.82) ; v2(1830.71,3704.72) 1933.07,3807.09 2476.38,3807.09 2523.62,3854.33 U11.29@2523.62,3901.57 v2(2523.62,3952.42)
BUS_D25: U4.G6 U7.44 U11.30 | length 4278.5
  Top Layer w7.87: v1(1208.66,1751.97) U4.G6@1228.35,1732.28
  MidLayer2 w5: v2(1834.65,3948.82) 1834.65,3854.33 1862.2,3826.77 v2(1862.2,3704.72)
  MidLayer3 w5: v1(1208.66,1751.97) 1228.35,1771.65 1228.35,2129.92 1322.83,2224.41 1322.83,2263.78 1397.64,2338.58 1633.86,2338.58 1677.17,2381.89 1677.17,2724.41 2003.94,3051.18 2031.5,3051.18 2070.87,3090.55 2070.87,3212.6 2204.72,3346.46 2440.94,3346.46 2472.44,3377.95 2472.44,3385.83 2484.25,3397.64 2484.25,3417.32 2490.16,3423.23 2543.31,3476.38 2543.31,3507.87 2535.43,3515.75 2535.43,3661.42 2562.99,3688.98 2562.99,3830.71 2574.8,3842.52 2574.8,3858.27 2555.12,3877.95 v2(2555.12,3952.76)
  Bottom Layer w5: U7.44@1834.65,3901.57 v2(1834.65,3948.82) ; v2(1862.2,3704.72) 1952.76,3795.28 2519.68,3795.28 2543.31,3818.9 2543.31,3834.65 2535.43,3842.52 2535.43,3862.2 2555.12,3881.89 v2(2555.12,3952.76)
BUS_D26: U4.G9 U7.45 U11.31 | length 4097
  Top Layer w7.87: v1(1326.77,1751.97) U4.G9@1346.46,1732.28
  MidLayer2 w5: v2(1866.14,3948.82) 1866.14,3877.95 1885.83,3858.27 1885.83,3842.52 1877.95,3834.65 1877.95,3818.9 1893.7,3803.15 v2(1893.7,3704.72)
  MidLayer3 w5: v1(1326.77,1751.97) 1307.09,1771.66 1307.09,2031.5 1307.09,2039.37 1307.09,2059.06 1362.2,2114.17 1362.2,2240.16 1448.82,2326.77 1637.8,2326.77 1688.98,2377.95 1688.98,2708.66 1964.57,2984.25 2051.18,2984.25 2082.68,3015.75 2082.68,3209.65 2089.57,3216.54 2207.68,3334.65 2476.38,3334.65 2511.81,3370.08 2511.81,3389.76 2507.87,3393.7 2507.87,3417.32 2566.93,3476.38 2566.93,3507.87 2574.8,3515.75 2574.8,3590.55 2590.55,3606.3 2590.55,3677.17 2582.68,3685.04 2582.68,3704.72 2586.61,3708.66 v2(2586.61,3826.77)
  Bottom Layer w5: U7.45@1866.14,3901.57 v2(1866.14,3948.82) ; v2(1893.7,3704.72) 1972.44,3783.46 2543.31,3783.46 v2(2586.61,3826.77) U11.31@2586.61,3901.57
BUS_D27: U4.G13 U7.47 U11.32 | length 4240.1
  Top Layer w7.87: v1(1484.25,1751.97) U4.G13@1503.94,1732.28
  MidLayer2 w5: v2(1925.2,3704.72) 1925.2,3818.9 1948.82,3842.52 1948.82,3858.27 1929.13,3877.95 v2(1929.13,3972.44)
  MidLayer3 w5: v1(1484.25,1751.97) 1464.57,1771.66 1464.57,1836.62 1464.57,1958.66 1476.38,1970.47 1476.38,2031.5 1476.38,2039.37 1476.38,2181.1 1519.68,2224.41 1720.47,2224.41 1740.16,2244.09 ; 1736.22,2240.16 1740.16,2244.09 ; v2(2618.11,3850.39) 2618.11,3708.66 2622.05,3704.72 2622.05,3685.04 2614.17,3677.17 2614.17,3551.18 2598.43,3535.43 2598.43,3515.75 2606.3,3507.87 2606.3,3472.44 2559.06,3425.2 2559.06,3385.83 2578.74,3366.14 2578.74,3149.61 2523.62,3094.49 2480.31,3094.49 2468.5,3082.68 2468.5,3027.56 2456.69,3015.75 2377.95,3015.75 2318.9,2956.69 2318.9,2905.51 2299.21,2885.83 2137.8,2885.83 2114.17,2909.45 1972.44,2909.45 1803.15,2740.16 1803.15,2681.1 1783.46,2661.42 1783.46,2342.52 1728.35,2287.4 1728.35,2275.59 1740.16,2263.78 1740.16,2244.09
  Bottom Layer w5: v2(1925.2,3704.72) 1992.13,3771.65 2559.05,3771.65 2618.11,3830.71 v2(2618.11,3850.39) U11.32@2618.11,3901.57 ; U7.47@1929.13,3901.57 v2(1929.13,3972.44)
BUS_D28: U4.G15 U7.48 U11.35 | length 4351.1
  Top Layer w7.87: U4.G15@1582.68,1732.28 v1(1602.36,1751.97)
  MidLayer2 w5: v2(1956.69,3704.72) 1956.69,3795.28 1980.31,3818.9 1980.31,3834.65 1960.63,3854.33 v2(1960.63,3972.44)
  MidLayer3 w5: v1(1602.36,1751.97) 1622.05,1771.66 1622.05,1948.82 1645.67,1972.44 1645.67,2031.5 1645.67,2039.37 1645.67,2094.49 1740.16,2188.98 1814.96,2188.98 1866.14,2240.16 1866.14,2263.78 1854.33,2275.59 1854.33,2287.4 1901.57,2334.65 1901.57,2669.29 1885.83,2685.04 1885.83,2696.85 1996.06,2807.09 2468.5,2807.09 2732.28,3070.87 2732.28,3507.87 2724.41,3515.75 2724.41,3531.49 2732.28,3539.37 2732.28,3559.06 2716.54,3574.8 2716.54,3677.17 2708.66,3685.04 2708.66,3704.72 2712.6,3708.66 2712.6,3799.21 2732.28,3818.9 2732.28,3834.65 2712.6,3854.33 v2(2712.6,3952.76)
  Bottom Layer w5: v2(1956.69,3704.72) 2011.81,3759.84 2618.11,3759.84 2712.6,3854.33 U11.35@2712.6,3901.57 v2(2712.6,3952.76) ; v2@1956.69,3972.44 v2(1960.63,3972.44) U7.48@1960.63,3901.57
BUS_D29: U4.G17 U7.50 U11.36 | length 4350
  Top Layer w7.87: U4.G17@1661.42,1732.28 v1(1681.1,1751.97)
  MidLayer2 w5: v2(1988.19,3704.72) 1988.19,3763.78 2043.31,3818.9 2043.31,3834.65 2023.62,3854.33 v2(2023.62,3948.82)
  MidLayer3 w5: v1(1681.1,1751.97) 1700.79,1771.65 1700.79,2031.5 1700.79,2039.37 1700.79,2078.74 1724.41,2102.36 1759.84,2102.36 1889.76,2232.28 1917.32,2232.28 1929.13,2244.09 1929.13,2263.78 1917.32,2275.59 1917.32,2287.4 1952.76,2322.83 1952.76,2700.79 2035.43,2783.46 2476.38,2783.46 2763.78,3070.87 2763.78,3401.57 2795.28,3433.07 2795.28,3507.87 2779.53,3523.62 2771.65,3523.62 2751.97,3543.31 2751.97,3559.06 2740.16,3570.87 2740.16,3677.17 2748.03,3685.04 2748.03,3704.72 2744.09,3708.66 2744.09,3822.83 2763.78,3842.52 2763.78,3858.27 2744.09,3877.95 v2(2744.09,3976.38)
  Bottom Layer w5: v2(1988.19,3704.72) 2031.5,3748.03 2661.42,3748.03 2732.28,3818.9 2732.28,3834.65 2724.41,3842.52 2724.41,3862.2 2744.09,3881.89 U11.36@2744.09,3901.57 v2(2744.09,3976.38) ; U7.50@2023.62,3901.57 v2(2023.62,3948.82)
BUS_D30: U4.H19 U7.51 U11.37 | length 4239
  Top Layer w7.87: U4.H19@1740.16,1692.91 v1(1759.84,1712.6)
  MidLayer2 w5: v2(2019.68,3704.72) 2019.68,3767.72 2066.93,3814.96 2066.93,3834.65 2074.8,3842.52 2074.8,3858.27 2055.12,3877.95 v2(2055.12,3948.82)
  MidLayer3 w5: v1(1759.84,1712.6) 1779.53,1732.28 1779.53,1972.44 1803.15,1996.06 1803.15,2031.5 1803.15,2039.37 1803.15,2114.17 1897.64,2208.66 1956.69,2208.66 1992.12,2244.09 1992.12,2263.78 1980.31,2275.59 1980.31,2295.27 2055.12,2370.08 2055.12,2669.29 2145.67,2759.84 2484.25,2759.84 2787.4,3062.99 2787.4,3393.7 2818.9,3425.2 2818.9,3507.87 2826.77,3515.75 2826.77,3566.93 2779.53,3614.17 2779.53,3677.17 2771.65,3685.04 2771.65,3704.72 2775.59,3708.66 2775.59,3795.28 2795.28,3814.96 2795.28,3834.65 2775.59,3854.33 v2(2775.59,3952.76)
  Bottom Layer w5: v2(2019.68,3704.72) 2051.18,3736.22 2669.29,3736.22 2755.9,3822.83 2755.9,3834.65 2775.59,3854.33 U11.37@2775.59,3901.57 v2(2775.59,3952.76) ; U7.51@2055.12,3901.57 v2(2055.12,3948.82)
BUS_D31: U4.G21 U7.53 U11.38 | length 4190.5
  Top Layer w7.87: U4.G21@1818.9,1732.28 v1(1838.58,1751.97)
  MidLayer2 w5: v2(2051.18,3704.72) 2051.18,3755.91 2137.8,3842.52 2137.8,3862.2 2118.11,3881.89 v2(2118.11,3948.82)
  MidLayer3 w5: v1(1838.58,1751.97) 1858.27,1771.65 1858.27,1972.44 1877.95,1992.13 1877.95,2031.5 1877.95,2039.37 1877.95,2066.93 1964.57,2153.54 2055.12,2244.09 2055.12,2263.78 2043.3,2275.59 2043.3,2291.34 2078.74,2326.77 2078.74,2661.42 2153.54,2736.22 2492.12,2736.22 2818.9,3062.99 2818.9,3393.7 2858.27,3433.07 2858.27,3507.87 2850.39,3515.75 2850.39,3531.5 2866.14,3547.24 2866.14,3562.99 2803.15,3625.98 2803.15,3677.17 2811.02,3685.04 2811.02,3704.72 2807.09,3708.66 2807.09,3822.83 2826.77,3842.52 2826.77,3858.27 2807.09,3877.95 v2(2807.09,3952.76)
  Bottom Layer w5: v2(2051.18,3704.72) 2070.87,3724.41 2704.72,3724.41 2795.28,3814.96 2795.28,3834.65 2787.4,3842.52 2787.4,3862.2 2807.09,3881.89 U11.38@2807.09,3901.57 v2(2807.09,3952.76) ; U7.53@2118.11,3901.57 v2(2118.11,3948.82)
BUS_FLASH_NBUSY: U3.A4 U4.J25 | length 1809.8
  Top Layer w5: U4.J25@1976.38,1653.54 1996.06,1673.23 2031.5,1673.23 2043.31,1661.42 2078.74,1661.42 2090.55,1661.42 2185.04,1661.42 2287.4,1763.78 2287.4,2011.81 2346.46,2070.87 2433.07,2157.48 2433.07,2263.78 2425.2,2271.65 2425.2,2291.34 2452.76,2318.9 2452.76,2606.3 2511.81,2665.35 2511.81,2818.9 2570.87,2877.95 2570.87,2996.07 v1(2527.56,3035.43)
  Top Layer w7.87: U3.A4@2507.87,3056.1 v1(2527.56,3035.43)
BUS_FLASH_NCS: U3.F2 U4.B19 | length 1685.2
  Top Layer w5: U4.B19@1740.16,1929.13 1759.84,1948.82 1759.84,1980.31 1740.16,2000 1740.16,2031.5 1740.16,2039.37 1740.16,2060.04 1728.35,2071.85 1728.35,2173.23 1803.15,2248.03 1803.15,2263.78 1795.27,2271.65 1795.27,2287.4 2055.12,2547.24 2055.12,2716.54 2114.17,2775.59 2114.17,2956.69 2129.92,2972.44 2129.92,3122.05 2212.6,3204.72 2271.65,3204.72 2291.34,3185.04 2291.34,3161.42 2299.21,3153.54 v1(2330.71,3153.54) ; U3.F2@2310.03,3134.85 U3.F2@2311.02,3134.84
  Top Layer w7.87: U3.F2@2311.02,3134.84 v1(2330.71,3153.54)
BUS_FLASH_NRESET: U3.B5 U4.N23 | length 2073
  Top Layer w7.87: U4.N23@1897.64,1496.06 v1(1917.33,1515.75) ; v1(2448.82,3035.43) U3.B5@2468.5,3016.73
  MidLayer1 w5: v1(1917.33,1515.75) 2078.74,1515.75 2090.55,1515.75 2122.05,1515.75 2222.93,1616.63 2222.93,1640.26 2322.83,1740.16 2322.83,2090.55 2456.69,2224.41 2496.06,2224.41 2519.68,2248.03 2519.68,2263.78 2543.31,2287.4 2543.31,2740.16 2559.06,2755.91 2559.06,3000 2543.31,3015.75 2507.87,3015.75 2488.19,3035.43 v1(2448.82,3035.43)
BUS_NBE0: RN1.6 RN4.7 U4.F11 U6.15 U10.39 | length 4268.9
  Top Layer w5: U6.15@1771.65,3452.75 v2(1771.65,3503.93) ; v2(2429.13,3850.39) U10.39@2429.13,3901.57
  Top Layer w7.87: v1(1405.51,1791.34) U4.F11@1425.2,1771.65
  MidLayer2 w5: v1(1405.51,1791.34) 1385.83,1811.02 1385.83,2031.49 1385.83,2039.37 1385.83,2200.79 1425.2,2240.16 1425.2,2259.84 1413.38,2271.65 1413.38,2283.46 1444.88,2314.96 1614.17,2314.96 1681.1,2381.89 1681.1,2681.1 1736.22,2736.22 2023.62,2736.22 2102.36,2814.96 2102.36,2988.19 2129.92,3015.75 2129.92,3228.35 2370.08,3468.5 2417.32,3468.5 2440.94,3492.13 2440.94,3507.87 2448.82,3515.75 2448.82,3531.5 2425.2,3555.12 2425.2,3677.17 2433.07,3685.04 2433.07,3704.72 2429.13,3708.66 v2(2429.13,3850.39) ; v1(1742.14,3311.02) 1742.14,3376 1771.65,3405.51 v2(1771.65,3503.93)
  MidLayer3 w5: v2(1771.65,3503.93) 1771.65,3657.49 1748.03,3681.1 1748.03,3767.72 1862.2,3881.89 2397.64,3881.89 v2(2429.13,3850.39)
  Bottom Layer w5: RN1.6@1688.58,3311.02 v1(1742.14,3311.02) RN4.7@1779.53,3311.02 RN4.7@1779.92,3311.02
BUS_NBE1: RN3.5 RN5.8 U4.E10 U6.39 U10.40 | length 3939.2
  Top Layer w5: U6.39@1803.14,3901.57 v2(1803.14,3850.39) 1803.14,3818.9 1818.89,3803.15 2374.02,3803.15 v2(2397.64,3826.77) U10.40@2397.64,3901.57
  Top Layer w7.87: v1(1366.14,1830.71) U4.E10@1385.83,1811.02
  MidLayer2 w5: v1(1366.14,1830.71) 1346.46,1850.39 1346.46,2031.5 1346.46,2039.37 1346.46,2220.47 1397.64,2271.65 1397.64,2283.47 1440.94,2326.77 1610.24,2326.77 1669.29,2385.83 1669.29,2685.04 1732.28,2748.03 2015.75,2748.03 2090.55,2822.83 2090.55,2996.06 2118.11,3023.62 2118.11,3232.28 2366.14,3480.32 2409.45,3480.32 2417.32,3488.19 2417.32,3507.87 2405.51,3519.68 2405.51,3673.23 2393.7,3685.04 2393.7,3704.72 2397.64,3708.66 v2(2397.64,3826.77)
  MidLayer3 w5: v1@1617.92,4055.11 v1(1618.11,4055.11) 1653.55,4055.11 1708.66,4000 1708.66,3944.88 v2(1803.14,3850.39)
  Bottom Layer w5: RN3.5@1586.22,4055.11 v1(1618.11,4055.11) RN5.8@1676.19,4055.12 RN5.8@1677.17,4055.11
BUS_NBE2: RN1.5 RN4.8 U4.F18 U7.15 U11.39 | length 4926.9
  Top Layer w7.87: U4.F18@1700.79,1771.65 v1(1720.47,1791.34)
  MidLayer2 w5: v1(1720.47,1791.34) 1700.79,1811.02 1700.79,2031.49 1700.79,2039.37 1700.79,2051.18 1881.89,2232.28 1921.26,2232.28 1984.25,2295.28 1984.25,2700.79 1996.06,2712.6 2035.43,2712.6 2125.98,2803.15 2125.98,2976.38 2181.1,3031.5 2181.1,3177.17 2228.35,3224.41 2460.63,3224.41 2476.38,3208.66 2716.54,3208.66 2862.2,3354.33 2862.2,3374.02 2881.89,3393.7 2881.89,3507.87 2889.76,3515.75 2889.76,3531.5 2881.89,3539.37 2881.89,3732.28 2858.27,3755.91 2858.27,3834.65 2838.58,3854.33 v2(2838.58,3976.38)
  MidLayer3 w5: v2(1708.66,3377.95) 1708.66,3409.45 1791.34,3492.13 1791.34,3511.81 1783.46,3519.68 1783.46,3688.98 v2(1799.21,3704.72)
  Bottom Layer w5: U7.15@1708.66,3452.76 v2(1708.66,3377.95) 1708.66,3362.2 1688.98,3342.52 1688.98,3331.1 1688.58,3330.71 RN4.8@1779.53,3330.71 ; v2@1799.21,3696.85 1811.02,3685.04 2078.74,3685.04 2106.3,3712.6 2712.6,3712.6 2818.9,3818.9 2818.9,3834.65 2838.58,3854.33 U11.39@2838.58,3901.57 v2(2838.58,3976.38)
BUS_NBE3: RN3.6 RN5.7 U4.E18 U7.39 U11.40 | length 5006.7
  Top Layer w7.87: U4.E18@1700.79,1811.02 v1(1720.47,1830.71)
  MidLayer1 w5: v2(1767.72,3704.72) 1787.4,3685.04 v2(2314.96,3685.04)
  MidLayer2 w5: v2(1677.17,3850.39) 1677.17,3795.28 v2(1767.72,3704.72) ; v1(1720.47,1830.71) 1740.16,1850.39 1740.16,2031.5 1740.16,2039.37 1740.16,2070.86 1889.76,2220.47 1972.44,2220.47 2023.62,2271.65 2023.62,2291.34 2011.81,2303.15 2011.81,2669.29 2137.8,2795.28 2137.8,2968.5 2192.91,3023.62 2192.91,3173.23 2232.28,3212.6 2456.69,3212.6 2472.44,3196.85 2748.03,3196.85 2795.28,3244.1 2877.95,3244.1 2889.76,3255.91 2889.76,3311.02 2917.32,3338.58 2917.32,3377.95 2933.07,3393.7 2933.07,3511.81 2921.26,3523.62 2921.26,3574.8 2893.7,3602.36 2893.7,3750 2881.89,3761.81 2881.89,3834.65 2889.76,3842.52 2889.76,3866.14 2870.08,3885.83 v2(2870.08,3952.76)
  MidLayer3 w5: v1@1641.54,4035.43 1696.85,3980.12 1696.85,3870.08 v2(1677.17,3850.39)
  Bottom Layer w5: RN3.6@1586.22,4035.43 v1(1639.78,4035.43) RN5.7@1676.19,4035.43 RN5.7@1677.56,4035.43 ; v2(1677.17,3850.39) U7.39@1677.17,3901.57 ; v2(2314.96,3685.04) 2358.27,3641.73 2704.72,3641.73 2858.27,3795.28 2858.27,3834.65 2850.39,3842.52 2850.39,3862.2 2870.08,3881.89 U11.40@2870.08,3901.57 v2(2870.08,3952.76)
BUS_NOE: U3.G2 U4.A20 U10.41 U11.41 | length 3861.8
  Top Layer w5: U4.A20@1779.53,1968.5 1779.53,2015.75 1763.78,2031.5 1763.78,2039.37 1763.78,2114.17 1778.54,2128.94 1778.54,2195.87 1818.9,2236.22 1818.9,2255.91 1834.64,2271.65 1834.64,2279.53 2066.93,2511.81 2066.93,2708.66 2125.98,2767.72 2125.98,2952.76 2141.73,2968.5 2141.73,3118.11 2216.54,3192.91 2240.16,3192.91 2251.97,3181.1 v1@2251.97,3154.53 ; v1@2255.91,3150.59 2255.91,3153.54 v1@2255.91,3154.53 ; v2(2366.14,3850.39) U10.41@2366.14,3901.57
  Top Layer w7.87: v1@2251.97,3154.53 2252.46,3154.04 2255.91,3150.59 U3.G2@2271.65,3134.84
  MidLayer3 w5: v2(2901.58,3952.76) 2901.57,3854.33 2940.94,3814.96 2940.94,3559.06 2925.2,3543.31 2925.2,3523.62 2933.07,3515.75 2933.07,3393.7 2917.32,3377.95 2917.32,3314.96 2909.45,3307.09 v1(2909.45,3287.4)
  MidLayer4 w5: v1(2251.97,3153.54) 2251.97,3263.78 2303.15,3314.96 2881.89,3314.96 v1(2909.45,3287.4) ; v2(2366.14,3850.39) 2366.14,3814.96 2374.02,3807.09 2909.45,3807.09 2921.26,3818.9 2921.26,3834.65 2901.58,3854.33 v2(2901.58,3952.76)
  Bottom Layer w5: U11.41@2901.57,3901.57 v2(2901.58,3952.76)
BUS_NWE: RN1.7 RN4.6 U3.A5 U4.H26 U6.16 U7.16 U10.17 U11.17 | length 4802.4
  Top Layer w5: U6.16@1803.14,3452.75 U6.16@1803.14,3460.63 ; v2(1803.14,3527.55) U6.16@1803.14,3460.63 ; U4.H26@2015.75,1692.91 2031.49,1692.91 2047.24,1677.17 2078.74,1677.17 2090.55,1677.17 2181.1,1677.17 2275.59,1771.65 2275.59,2015.75 2393.7,2133.86 2393.7,2263.78 2401.57,2271.65 2401.57,2287.4 2440.94,2326.77 2440.94,2610.24 2500,2669.29 2500,2822.83 2559.06,2881.89 2559.06,2968.5 2529.53,2998.03 2510.82,3016.74 U3.A5@2507.87,3016.73 ; v1(2492.13,3377.95) 2468.5,3354.33 1917.32,3354.33 1893.7,3377.95 1799.21,3377.95 1783.46,3393.7 1783.46,3413.39 1803.15,3433.07 U6.16@1803.15,3452.76 U6.16@1803.15,3460.62 ; U10.17@2775.59,3452.76 2775.59,3472.44 2795.28,3492.13 2795.28,3507.87 2787.4,3515.75 2787.4,3535.43 v1(2807.09,3555.12)
  MidLayer1 w5: v1(2527.56,2996.06) 2507.87,2996.06 2488.19,3015.75 2440.94,3015.75 2429.13,3027.56 2429.13,3082.68 2417.32,3094.49 2397.64,3094.49 2389.76,3102.36 2389.76,3122.05 2401.57,3133.86 2417.32,3133.86 2429.13,3145.67 2429.13,3161.42 2440.94,3173.23 2492.13,3173.23 2515.75,3196.85 2728.35,3196.85 2799.21,3267.72 2799.21,3503.94 2787.4,3515.75 2787.4,3535.43 v1(2807.09,3555.12)
  MidLayer2 w5: v2(1677.17,3503.94) 1677.17,3433.07 1696.85,3413.39 1696.85,3397.64 1688.98,3389.76 1688.98,3322.83 v1(1720.47,3291.34)
  MidLayer4 w5: v2(1677.17,3503.94) 1720.47,3503.94 1744.09,3527.55 v2(1803.14,3527.55) ; v1(2492.13,3377.95) 2456.69,3377.95 2440.94,3393.7 2440.94,3413.39 2503.94,3476.38 2724.41,3476.38 v1@2805.12,3557.09
  Bottom Layer w5: U7.16@1677.17,3452.76 v2(1677.17,3503.94) ; RN1.7@1688.18,3291.34 v1(1720.47,3291.34) RN4.6@1779.53,3291.34 RN4.6@1779.92,3291.34 ; v1(2492.13,3377.95) U11.17@2492.13,3452.76
BUS_SDRAM_CKE: RN3.7 RN5.6 U4.G10 U6.37 U7.37 | length 3428.7
  Top Layer w5: v2(1866.14,3850.39) U6.37@1866.14,3901.57
  Top Layer w7.87: v1(1366.14,1751.97) U4.G10@1385.83,1732.28
  MidLayer3 w5: v2(1614.17,3948.82) 1614.17,3976.38 1618.9,3981.11 v1@1618.9,4015.75 ; v2(1866.14,3850.39) 1866.14,3818.9 1948.82,3736.22 2098.43,3736.22 2192.91,3641.73 v1(2192.91,3397.64)
  MidLayer4 w5: v1(1366.14,1751.97) 1385.83,1771.65 1492.13,1771.65 1507.87,1787.4 1507.87,1929.13 1535.43,1956.69 1535.43,2031.5 1535.43,2039.37 1535.43,2070.87 1555.12,2090.55 1555.12,2118.11 1728.35,2291.34 1728.35,2606.3 1814.96,2692.91 1814.96,2704.72 1913.39,2803.15 2090.55,2803.15 2129.92,2842.52 2129.92,3248.03 2192.91,3311.02 v1(2192.91,3397.64) ; v2(1614.17,3948.82) 1637.8,3972.44 1685.04,3972.44 1755.91,3901.57 1814.96,3901.57 v2(1866.14,3850.39)
  Bottom Layer w5: RN3.7@1586.22,4015.75 v1(1617.14,4015.75) RN5.6@1676.19,4015.75 RN5.6@1677.56,4015.75 ; U7.37@1614.17,3901.57 v2(1614.17,3948.82)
